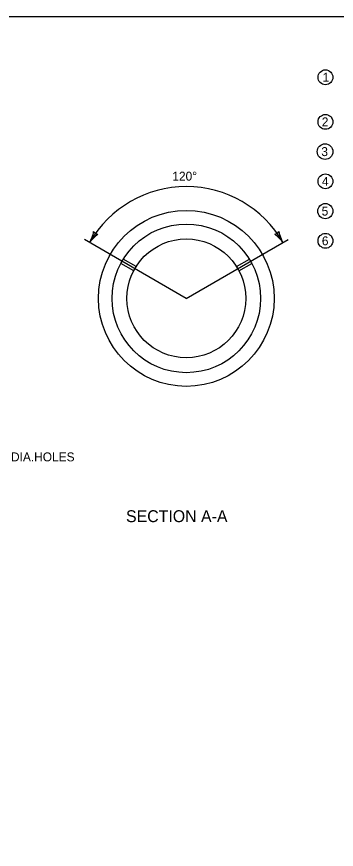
# Model space of a CAD drawing. Extents: x 49991.4 to 50021, y 49987.6 to 50011.4.
# Drawn here: x 50005.23 to 50007.38, y 49993.4 to 49999 of the extents above; entities that cross this region are included whole.
import ezdxf

# ---------------------------------------------------------------- set-up
doc = ezdxf.new("R2010")
doc.units = 0
for name, color, linetype in [('Level 1', 7, 'Continuous'), ('Level 2', 7, 'Continuous'), ('Level 3', 7, 'Continuous'), ('Level 4', 7, 'Continuous')]:
    doc.layers.add(name, color=color, linetype=linetype)

msp = doc.modelspace()

# ---------------------------------------------------------------- linework, layer by layer
at = {"layer": 'Level 1'}
msp.add_lwpolyline([(49999.3835, 49998.9992), (50016.7501, 49998.9992), (50016.7501, 49987.7988), (49999.3835, 49987.7988)], close=True, dxfattribs=at)
for radius in [0.5917, 0.5, 0.4]:
    msp.add_circle((50006.3742, 49997.1046), radius, dxfattribs=at)
at = {"layer": 'Level 2'}
for centre, radius in [((50007.3115, 49998.5915), 0.05), ((50007.3115, 49998.2915), 0.05), ((50007.3087, 49998.0915), 0.0528), ((50007.3115, 49997.8915), 0.05), ((50007.3105, 49997.6915), 0.051), ((50007.3115, 49997.4915), 0.05)]:
    msp.add_circle(centre, radius, dxfattribs=at)
at = {"layer": 'Level 3'}
for q in [(50005.6885, 49997.5005), (50007.0599, 49997.5005)]:
    msp.add_line((50006.3742, 49997.1046), q, dxfattribs=at)
for centre, radius, start, end in [((50006.3742, 49997.1046), 0.7518, 30, 150), ((50005.5212, 49997.5967), 0.233, 330.0733, 349.3232), ((50005.905, 49997.3526), 0.2223, 124.702, 144.8855), ((50005.7925, 49997.5883), 0.0548, 219.3848, 255.1072), ((50006.9558, 49997.5883), 0.0548, 284.9216, 320.6439), ((50006.8358, 49997.3448), 0.233, 35.61, 54.8599), ((50007.2169, 49997.5931), 0.2223, 190.2387, 210.4223)]:
    msp.add_arc(centre, radius, start, end, dxfattribs=at)
at = {"layer": 'Level 4'}
for p, q in [((50006.0364, 49997.3189), (50005.9497, 49997.3689)), ((50006.7119, 49997.3189), (50006.7986, 49997.3689)), ((50006.0197, 49997.29), (50005.9331, 49997.34)), ((50006.7286, 49997.29), (50006.8153, 49997.34))]:
    msp.add_line(p, q, dxfattribs=at)

# ---------------------------------------------------------------- texts
at = {"layer": 'Level 2'}
for s, height, p in [('1', 0.06, (50007.2918, 49998.5615)), ('2', 0.06, (50007.2864, 49998.2615)), ('3', 0.06, (50007.2835, 49998.0615)), ('4', 0.06, (50007.2875, 49997.8615)), ('5', 0.06, (50007.2856, 49997.6615)), ('6', 0.06, (50007.287, 49997.4615)), ('CONTRACTOR TO DRILL 1" [25.4] DIA.HOLES', 0.06, (50003.9033, 49996.0083)), ('SECTION A-A', 0.08, (50005.968, 49995.5996))]:
    msp.add_text(s, height=height, dxfattribs=at).set_placement(p)
msp.add_text('120°', height=0.06, rotation=360, dxfattribs=at).set_placement((50006.2801, 49997.8964))

doc.saveas('drawing.dxf')
